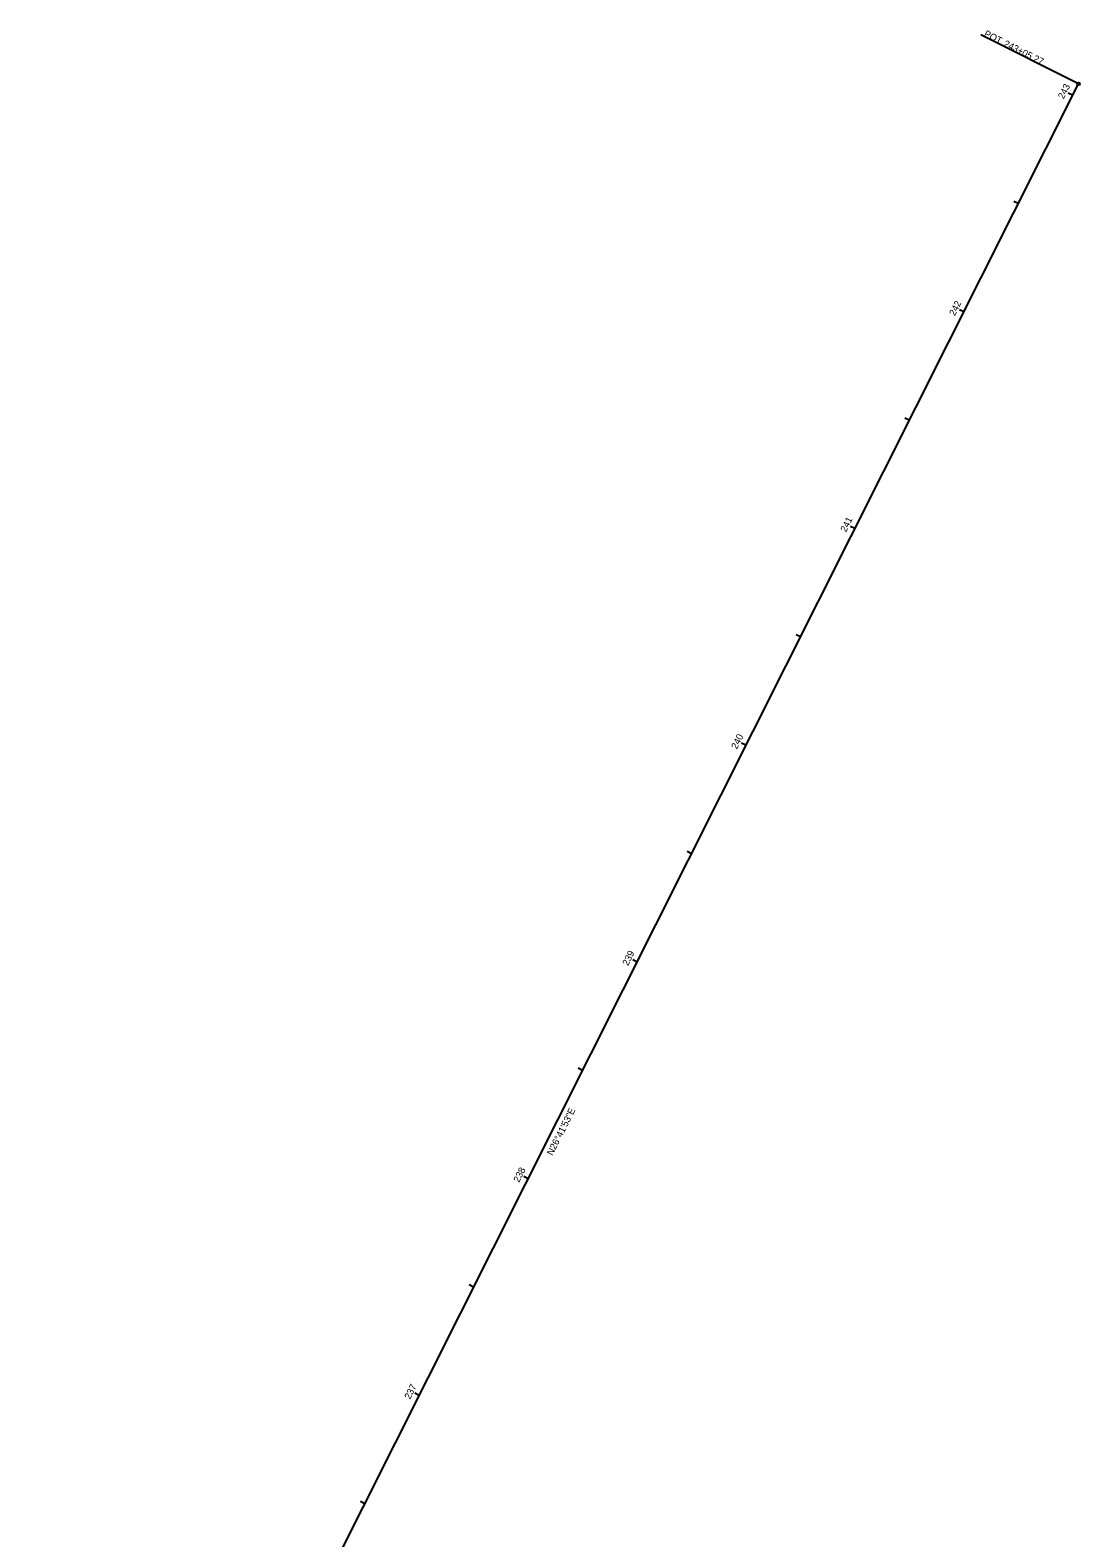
# Model space of a CAD drawing. Extents: x 1454426 to 1455277, y 587472 to 590476.
# Drawn here: x 1454669 to 1455102, y 589855 to 590476 of the extents above; entities that cross this region are included whole.
import ezdxf

# ---------------------------------------------------------------- set-up
doc = ezdxf.new("R2010")
doc.units = 0
for name, color, linetype in [('Default', 7, 'Continuous'), ('GT_Target_Soil_Boring', 7, 'Continuous'), ('SC_Scratch1', 7, 'Continuous'), ('SC_Scratch2', 7, 'Continuous'), ('SC_Scratch3', 7, 'Continuous')]:
    doc.layers.add(name, color=color, linetype=linetype)

msp = doc.modelspace()

# ---------------------------------------------------------------- linework, layer by layer
at = {"layer": 'Default'}
for centre in [(1455101.66, 590454.22), (1455101.66, 590454.22), (1455101.66, 590454.22), (1455099.29, 590449.51), (1455099.29, 590449.51), (1455099.29, 590449.51), (1455054.36, 590360.17), (1455054.36, 590360.17), (1455054.36, 590360.17), (1455009.43, 590270.84), (1455009.43, 590270.84), (1455009.43, 590270.84), (1454964.5, 590181.5), (1454964.5, 590181.5), (1454964.5, 590181.5), (1454919.57, 590092.16), (1454919.57, 590092.16), (1454919.57, 590092.16), (1454885.44, 590024.29), (1454885.44, 590024.29), (1454885.44, 590024.29), (1454874.65, 590002.82), (1454874.65, 590002.82), (1454874.65, 590002.82), (1454829.72, 589913.48), (1454829.72, 589913.48), (1454829.72, 589913.48)]:
    msp.add_circle(centre, 0.0000833, dxfattribs=at)
at = {"layer": 'GT_Target_Soil_Boring'}
msp.add_line((1454669.23, 589594.35), (1455101.66, 590454.22), dxfattribs=at)
at = {"layer": 'SC_Scratch1'}
for p, q in [((1455101.66, 590454.22), (1455061.46, 590474.44)), ((1455099.29, 590449.51), (1455097.5, 590450.41)), ((1455076.83, 590404.84), (1455075.04, 590405.74)), ((1455054.36, 590360.17), (1455052.57, 590361.07)), ((1455031.9, 590315.5), (1455030.11, 590316.4)), ((1455009.43, 590270.84), (1455007.65, 590271.73)), ((1454986.97, 590226.17), (1454985.18, 590227.06)), ((1454964.5, 590181.5), (1454962.72, 590182.4)), ((1454942.04, 590136.83), (1454940.25, 590137.73)), ((1454919.57, 590092.16), (1454917.79, 590093.06)), ((1454897.11, 590047.49), (1454895.32, 590048.39)), ((1454874.65, 590002.82), (1454872.86, 590003.72)), ((1454852.18, 589958.15), (1454850.39, 589959.05)), ((1454829.72, 589913.48), (1454827.93, 589914.38)), ((1454807.25, 589868.81), (1454805.47, 589869.71))]:
    msp.add_line(p, q, dxfattribs=at)
msp.add_circle((1455101.66, 590454.22), 0.6, dxfattribs=at)
at = {"layer": 'SC_Scratch2'}
for p, q in [((1455101.66, 590454.22), (1455061.46, 590474.44)), ((1455099.29, 590449.51), (1455097.5, 590450.41)), ((1455076.83, 590404.84), (1455075.04, 590405.74)), ((1455054.36, 590360.17), (1455052.57, 590361.07)), ((1455031.9, 590315.5), (1455030.11, 590316.4)), ((1455009.43, 590270.84), (1455007.65, 590271.73)), ((1454986.97, 590226.17), (1454985.18, 590227.06)), ((1454964.5, 590181.5), (1454962.72, 590182.4)), ((1454942.04, 590136.83), (1454940.25, 590137.73)), ((1454919.57, 590092.16), (1454917.79, 590093.06)), ((1454897.11, 590047.49), (1454895.32, 590048.39)), ((1454874.65, 590002.82), (1454872.86, 590003.72)), ((1454852.18, 589958.15), (1454850.39, 589959.05)), ((1454829.72, 589913.48), (1454827.93, 589914.38)), ((1454807.25, 589868.81), (1454805.47, 589869.71))]:
    msp.add_line(p, q, dxfattribs=at)
msp.add_circle((1455101.66, 590454.22), 0.6, dxfattribs=at)
at = {"layer": 'SC_Scratch3'}
for p, q in [((1455101.66, 590454.22), (1455061.46, 590474.44)), ((1455099.29, 590449.51), (1455097.5, 590450.41)), ((1455076.83, 590404.84), (1455075.04, 590405.74)), ((1455054.36, 590360.17), (1455052.57, 590361.07)), ((1455031.9, 590315.5), (1455030.11, 590316.4)), ((1455009.43, 590270.84), (1455007.65, 590271.73)), ((1454986.97, 590226.17), (1454985.18, 590227.06)), ((1454964.5, 590181.5), (1454962.72, 590182.4)), ((1454942.04, 590136.83), (1454940.25, 590137.73)), ((1454919.57, 590092.16), (1454917.79, 590093.06)), ((1454897.11, 590047.49), (1454895.32, 590048.39)), ((1454874.65, 590002.82), (1454872.86, 590003.72)), ((1454852.18, 589958.15), (1454850.39, 589959.05)), ((1454829.72, 589913.48), (1454827.93, 589914.38)), ((1454807.25, 589868.81), (1454805.47, 589869.71))]:
    msp.add_line(p, q, dxfattribs=at)
msp.add_circle((1455101.66, 590454.22), 0.6, dxfattribs=at)

# ---------------------------------------------------------------- texts
at = {"layer": 'SC_Scratch1'}
for s, rotation, p in [('POT', 333.30195, (1455062.43, 590474.01)), ('243+05.27', 333.30195, (1455070.58, 590469.9)), ('243', 63.30195, (1455095.55, 590447.74)), ('242', 63.30195, (1455050.66, 590358.37)), ('241', 63.30195, (1455005.8, 590269.18)), ('240', 63.30195, (1454960.75, 590179.71)), ('239', 63.30195, (1454915.84, 590090.4)), ('N26°41\'53"E', 63.30195, (1454884.71, 590012.14)), ('238', 63.30195, (1454870.9, 590001.04)), ('237', 63.30195, (1454825.94, 589911.64))]:
    msp.add_text(s, height=2.8, rotation=rotation, dxfattribs=at).set_placement(p)
at = {"layer": 'SC_Scratch2'}
for s, rotation, p in [('POT', 333.30195, (1455062.43, 590474.01)), ('243+05.27', 333.30195, (1455070.58, 590469.9)), ('243', 63.30195, (1455095.55, 590447.74)), ('242', 63.30195, (1455050.66, 590358.37)), ('241', 63.30195, (1455005.8, 590269.18)), ('240', 63.30195, (1454960.75, 590179.71)), ('239', 63.30195, (1454915.84, 590090.4)), ('N26°41\'53"E', 63.30195, (1454884.71, 590012.14)), ('238', 63.30195, (1454870.9, 590001.04)), ('237', 63.30195, (1454825.94, 589911.64))]:
    msp.add_text(s, height=2.8, rotation=rotation, dxfattribs=at).set_placement(p)
at = {"layer": 'SC_Scratch3'}
for s, rotation, p in [('POT', 333.30195, (1455062.43, 590474.01)), ('243+05.27', 333.30195, (1455070.58, 590469.9)), ('243', 63.30195, (1455095.55, 590447.74)), ('242', 63.30195, (1455050.66, 590358.37)), ('241', 63.30195, (1455005.8, 590269.18)), ('240', 63.30195, (1454960.75, 590179.71)), ('239', 63.30195, (1454915.84, 590090.4)), ('N26°41\'53"E', 63.30195, (1454884.71, 590012.14)), ('238', 63.30195, (1454870.9, 590001.04)), ('237', 63.30195, (1454825.94, 589911.64))]:
    msp.add_text(s, height=2.8, rotation=rotation, dxfattribs=at).set_placement(p)

doc.saveas('drawing.dxf')
